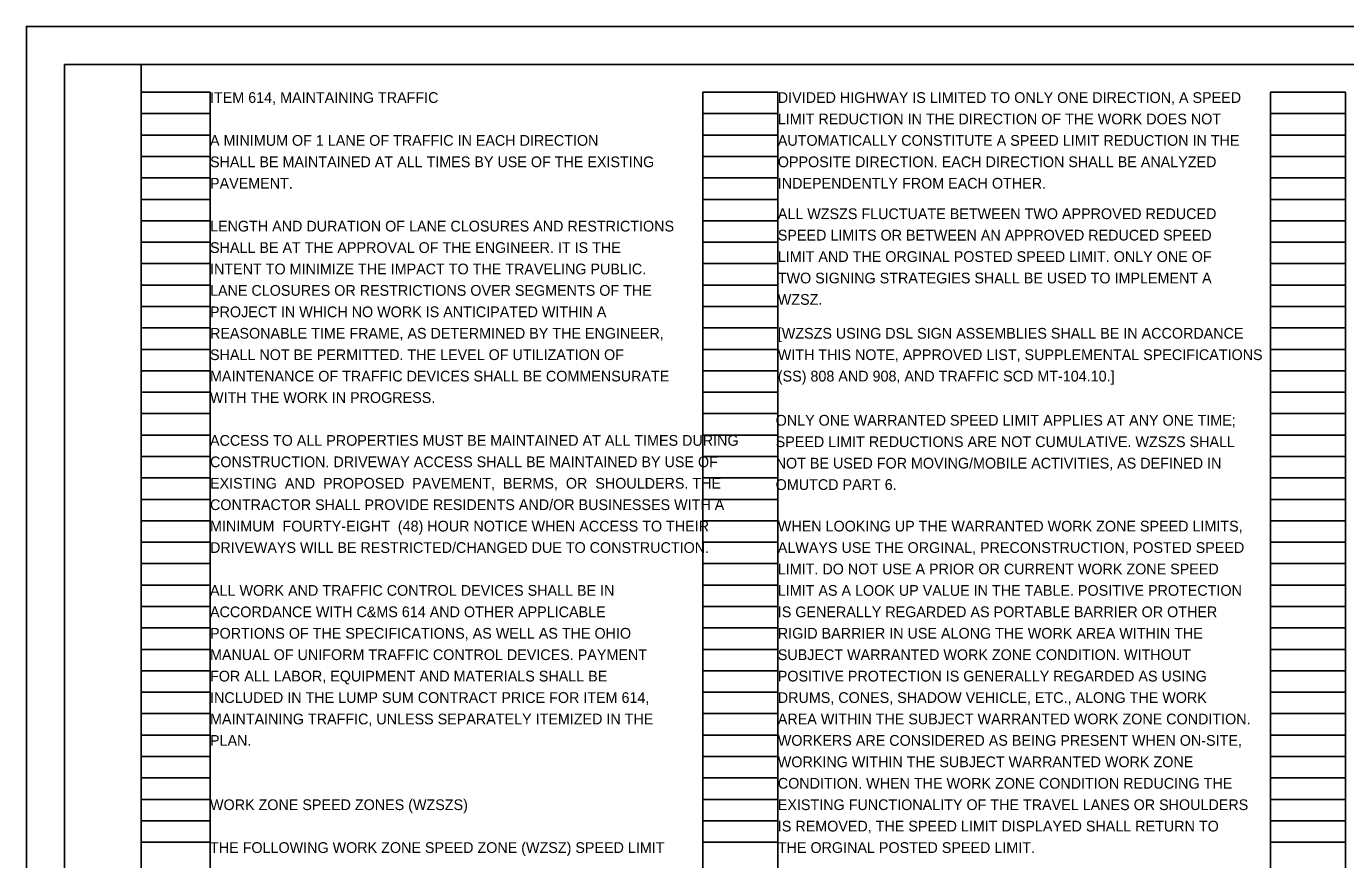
# Model space of a CAD drawing. Extents: x 0 to 34, y 0 to 22.
# Drawn here: x 0 to 17.24, y 11.11 to 22 of the extents above; entities that cross this region are included whole.
import ezdxf

# ---------------------------------------------------------------- set-up
doc = ezdxf.new("R2010")
doc.units = 0
for name, color, linetype in [('SH_Border', 7, 'Continuous'), ('SH_Cut_Line', 7, 'Continuous'), ('SH_Data', 7, 'Continuous'), ('SH_Text', 7, 'Continuous')]:
    doc.layers.add(name, color=color, linetype=linetype)

msp = doc.modelspace()

# ---------------------------------------------------------------- linework, layer by layer
at = {"layer": 'SH_Border'}
for points in [[(0.5, 21.5), (1.5, 21.5), (1.5, 0.5), (0.5, 0.5)], [(1.5, 21.5), (33.5, 21.5), (33.5, 0.5), (1.5, 0.5)]]:
    msp.add_lwpolyline(points, close=True, dxfattribs=at)
at = {"layer": 'SH_Cut_Line'}
msp.add_lwpolyline([(0, 0), (34, 0), (34, 22), (0, 22)], close=True, dxfattribs=at)
at = {"layer": 'SH_Data'}
for p, q in [((1.5, 0.98), (1.5, 21.14)), ((1.5, 21.14), (2.4, 21.14)), ((2.4, 0.98), (2.4, 21.14)), ((8.84, 0.98), (8.84, 21.14)), ((8.84, 21.14), (9.82, 21.14)), ((9.82, 0.98), (9.82, 21.14)), ((16.26, 0.98), (16.26, 21.14)), ((16.26, 21.14), (17.24, 21.14)), ((17.24, 0.98), (17.24, 21.14)), ((1.5, 20.86), (2.4, 20.86)), ((8.84, 20.86), (9.82, 20.86)), ((16.26, 20.86), (17.24, 20.86)), ((1.5, 20.58), (2.4, 20.58)), ((8.84, 20.58), (9.82, 20.58)), ((16.26, 20.58), (17.24, 20.58)), ((1.5, 20.3), (2.4, 20.3)), ((8.84, 20.3), (9.82, 20.3)), ((16.26, 20.3), (17.24, 20.3)), ((1.5, 20.02), (2.4, 20.02)), ((8.84, 20.02), (9.82, 20.02)), ((16.26, 20.02), (17.24, 20.02)), ((1.5, 19.74), (2.4, 19.74)), ((8.84, 19.74), (9.82, 19.74)), ((16.26, 19.74), (17.24, 19.74)), ((1.5, 19.46), (2.4, 19.46)), ((8.84, 19.46), (9.82, 19.46)), ((16.26, 19.46), (17.24, 19.46)), ((1.5, 19.18), (2.4, 19.18)), ((8.84, 19.18), (9.82, 19.18)), ((16.26, 19.18), (17.24, 19.18)), ((1.5, 18.9), (2.4, 18.9)), ((8.84, 18.9), (9.82, 18.9)), ((16.26, 18.9), (17.24, 18.9)), ((1.5, 18.62), (2.4, 18.62)), ((8.84, 18.62), (9.82, 18.62)), ((16.26, 18.62), (17.24, 18.62)), ((1.5, 18.34), (2.4, 18.34)), ((8.84, 18.34), (9.82, 18.34)), ((16.26, 18.34), (17.24, 18.34)), ((1.5, 18.06), (2.4, 18.06)), ((8.84, 18.06), (9.82, 18.06)), ((16.26, 18.06), (17.24, 18.06)), ((1.5, 17.78), (2.4, 17.78)), ((8.84, 17.78), (9.82, 17.78)), ((16.26, 17.78), (17.24, 17.78)), ((1.5, 17.5), (2.4, 17.5)), ((8.84, 17.5), (9.82, 17.5)), ((16.26, 17.5), (17.24, 17.5)), ((1.5, 17.22), (2.4, 17.22)), ((8.84, 17.22), (9.82, 17.22)), ((16.26, 17.22), (17.24, 17.22)), ((1.5, 16.94), (2.4, 16.94)), ((8.84, 16.94), (9.82, 16.94)), ((16.26, 16.94), (17.24, 16.94)), ((1.5, 16.66), (2.4, 16.66)), ((8.84, 16.66), (9.82, 16.66)), ((16.26, 16.66), (17.24, 16.66)), ((1.5, 16.38), (2.4, 16.38)), ((8.84, 16.38), (9.82, 16.38)), ((16.26, 16.38), (17.24, 16.38)), ((1.5, 16.1), (2.4, 16.1)), ((8.84, 16.1), (9.82, 16.1)), ((16.26, 16.1), (17.24, 16.1)), ((1.5, 15.82), (2.4, 15.82)), ((8.84, 15.82), (9.82, 15.82)), ((16.26, 15.82), (17.24, 15.82)), ((1.5, 15.54), (2.4, 15.54)), ((8.84, 15.54), (9.82, 15.54)), ((16.26, 15.54), (17.24, 15.54)), ((1.5, 15.26), (2.4, 15.26)), ((8.84, 15.26), (9.82, 15.26)), ((16.26, 15.26), (17.24, 15.26)), ((1.5, 14.98), (2.4, 14.98)), ((8.84, 14.98), (9.82, 14.98)), ((16.26, 14.98), (17.24, 14.98)), ((1.5, 14.7), (2.4, 14.7)), ((8.84, 14.7), (9.82, 14.7)), ((16.26, 14.7), (17.24, 14.7)), ((1.5, 14.42), (2.4, 14.42)), ((8.84, 14.42), (9.82, 14.42)), ((16.26, 14.42), (17.24, 14.42)), ((1.5, 14.14), (2.4, 14.14)), ((8.84, 14.14), (9.82, 14.14)), ((16.26, 14.14), (17.24, 14.14)), ((1.5, 13.86), (2.4, 13.86)), ((8.84, 13.86), (9.82, 13.86)), ((16.26, 13.86), (17.24, 13.86)), ((1.5, 13.58), (2.4, 13.58)), ((8.84, 13.58), (9.82, 13.58)), ((16.26, 13.58), (17.24, 13.58)), ((1.5, 13.3), (2.4, 13.3)), ((8.84, 13.3), (9.82, 13.3)), ((16.26, 13.3), (17.24, 13.3)), ((1.5, 13.02), (2.4, 13.02)), ((8.84, 13.02), (9.82, 13.02)), ((16.26, 13.02), (17.24, 13.02)), ((1.5, 12.74), (2.4, 12.74)), ((8.84, 12.74), (9.82, 12.74)), ((16.26, 12.74), (17.24, 12.74)), ((1.5, 12.46), (2.4, 12.46)), ((8.84, 12.46), (9.82, 12.46)), ((16.26, 12.46), (17.24, 12.46)), ((1.5, 12.18), (2.4, 12.18)), ((8.84, 12.18), (9.82, 12.18)), ((16.26, 12.18), (17.24, 12.18)), ((1.5, 11.9), (2.4, 11.9)), ((8.84, 11.9), (9.82, 11.9)), ((16.26, 11.9), (17.24, 11.9)), ((1.5, 11.62), (2.4, 11.62)), ((8.84, 11.62), (9.82, 11.62)), ((16.26, 11.62), (17.24, 11.62)), ((1.5, 11.34), (2.4, 11.34)), ((8.84, 11.34), (9.82, 11.34)), ((16.26, 11.34), (17.24, 11.34))]:
    msp.add_line(p, q, dxfattribs=at)

# ---------------------------------------------------------------- texts
at = {"layer": 'SH_Text'}
for s, p in [('ITEM 614, MAINTAINING TRAFFIC ', (2.4, 21)), ('DIVIDED HIGHWAY IS LIMITED TO ONLY ONE DIRECTION, A SPEED', (9.82, 21)), ('LIMIT REDUCTION IN THE DIRECTION OF THE WORK DOES NOT', (9.82, 20.72)), ('A MINIMUM OF 1 LANE OF TRAFFIC IN EACH DIRECTION', (2.4, 20.44)), ('AUTOMATICALLY CONSTITUTE A SPEED LIMIT REDUCTION IN THE', (9.82, 20.44)), ('SHALL BE MAINTAINED AT ALL TIMES BY USE OF THE EXISTING', (2.4, 20.16)), ('OPPOSITE DIRECTION. EACH DIRECTION SHALL BE ANALYZED', (9.82, 20.16)), ('PAVEMENT.', (2.4, 19.88)), ('INDEPENDENTLY FROM EACH OTHER.', (9.82, 19.88)), ('ALL WZSZS FLUCTUATE BETWEEN TWO APPROVED REDUCED', (9.82, 19.482)), ('LENGTH AND DURATION OF LANE CLOSURES AND RESTRICTIONS', (2.4, 19.32)), ('SPEED LIMITS OR BETWEEN AN APPROVED REDUCED SPEED', (9.82, 19.202)), ('SHALL BE AT THE APPROVAL OF THE ENGINEER. IT IS THE', (2.4, 19.04)), ('LIMIT AND THE ORGINAL POSTED SPEED LIMIT. ONLY ONE OF', (9.82, 18.922)), ('INTENT TO MINIMIZE THE IMPACT TO THE TRAVELING PUBLIC.', (2.4, 18.76)), ('LANE CLOSURES OR RESTRICTIONS OVER SEGMENTS OF THE', (2.4, 18.48)), ('TWO SIGNING STRATEGIES SHALL BE USED TO IMPLEMENT A', (9.82, 18.642)), ('WZSZ.', (9.82, 18.362)), ('PROJECT IN WHICH NO WORK IS ANTICIPATED WITHIN A', (2.4, 18.2)), ('REASONABLE TIME FRAME, AS DETERMINED BY THE ENGINEER,', (2.4, 17.92)), ('[WZSZS USING DSL SIGN ASSEMBLIES SHALL BE IN ACCORDANCE', (9.82, 17.92)), ('SHALL NOT BE PERMITTED. THE LEVEL OF UTILIZATION OF', (2.4, 17.64)), ('WITH THIS NOTE, APPROVED LIST, SUPPLEMENTAL SPECIFICATIONS', (9.82, 17.64)), ('MAINTENANCE OF TRAFFIC DEVICES SHALL BE COMMENSURATE', (2.4, 17.36)), ('(SS) 808 AND 908, AND TRAFFIC SCD MT-104.10.]', (9.82, 17.36)), ('WITH THE WORK IN PROGRESS.', (2.4, 17.08)), ('ONLY ONE WARRANTED SPEED LIMIT APPLIES AT ANY ONE TIME;', (9.792, 16.783)), ('ACCESS TO ALL PROPERTIES MUST BE MAINTAINED AT ALL TIMES DURING', (2.4, 16.52)), ('SPEED LIMIT REDUCTIONS ARE NOT CUMULATIVE. WZSZS SHALL', (9.792, 16.503)), ('CONSTRUCTION. DRIVEWAY ACCESS SHALL BE MAINTAINED BY USE OF', (2.4, 16.24)), ('NOT BE USED FOR MOVING/MOBILE ACTIVITIES, AS DEFINED IN', (9.792, 16.223)), ('EXISTING  AND  PROPOSED  PAVEMENT,  BERMS,  OR  SHOULDERS. THE', (2.4, 15.96)), ('OMUTCD PART 6.', (9.792, 15.943)), ('CONTRACTOR SHALL PROVIDE RESIDENTS AND/OR BUSINESSES WITH A', (2.4, 15.68)), ('MINIMUM  FOURTY-EIGHT  (48) HOUR NOTICE WHEN ACCESS TO THEIR', (2.4, 15.4)), ('WHEN LOOKING UP THE WARRANTED WORK ZONE SPEED LIMITS,', (9.82, 15.4)), ('DRIVEWAYS WILL BE RESTRICTED/CHANGED DUE TO CONSTRUCTION.', (2.4, 15.12)), ('ALWAYS USE THE ORGINAL, PRECONSTRUCTION, POSTED SPEED', (9.82, 15.12)), ('LIMIT. DO NOT USE A PRIOR OR CURRENT WORK ZONE SPEED', (9.82, 14.84)), ('ALL WORK AND TRAFFIC CONTROL DEVICES SHALL BE IN', (2.4, 14.56)), ('LIMIT AS A LOOK UP VALUE IN THE TABLE. POSITIVE PROTECTION', (9.82, 14.56)), ('ACCORDANCE WITH C&MS 614 AND OTHER APPLICABLE', (2.4, 14.28)), ('IS GENERALLY REGARDED AS PORTABLE BARRIER OR OTHER', (9.82, 14.28)), ('PORTIONS OF THE SPECIFICATIONS, AS WELL AS THE OHIO', (2.4, 14)), ('RIGID BARRIER IN USE ALONG THE WORK AREA WITHIN THE', (9.82, 14)), ('MANUAL OF UNIFORM TRAFFIC CONTROL DEVICES. PAYMENT', (2.4, 13.72)), ('SUBJECT WARRANTED WORK ZONE CONDITION. WITHOUT', (9.82, 13.72)), ('FOR ALL LABOR, EQUIPMENT AND MATERIALS SHALL BE', (2.4, 13.44)), ('POSITIVE PROTECTION IS GENERALLY REGARDED AS USING', (9.82, 13.44)), ('INCLUDED IN THE LUMP SUM CONTRACT PRICE FOR ITEM 614,', (2.4, 13.16)), ('DRUMS, CONES, SHADOW VEHICLE, ETC., ALONG THE WORK', (9.82, 13.16)), ('MAINTAINING TRAFFIC, UNLESS SEPARATELY ITEMIZED IN THE', (2.4, 12.88)), ('AREA WITHIN THE SUBJECT WARRANTED WORK ZONE CONDITION.', (9.82, 12.88)), ('PLAN.', (2.4, 12.6)), ('WORKERS ARE CONSIDERED AS BEING PRESENT WHEN ON-SITE,', (9.82, 12.6)), ('WORKING WITHIN THE SUBJECT WARRANTED WORK ZONE', (9.82, 12.32)), ('CONDITION. WHEN THE WORK ZONE CONDITION REDUCING THE', (9.82, 12.04)), ('WORK ZONE SPEED ZONES (WZSZS)', (2.4, 11.76)), ('EXISTING FUNCTIONALITY OF THE TRAVEL LANES OR SHOULDERS', (9.82, 11.76)), ('IS REMOVED, THE SPEED LIMIT DISPLAYED SHALL RETURN TO', (9.82, 11.48)), ('THE FOLLOWING WORK ZONE SPEED ZONE (WZSZ) SPEED LIMIT', (2.4, 11.2)), ('THE ORGINAL POSTED SPEED LIMIT.', (9.82, 11.2))]:
    msp.add_text(s, height=0.14, dxfattribs=at).set_placement(p)

doc.saveas('drawing.dxf')
